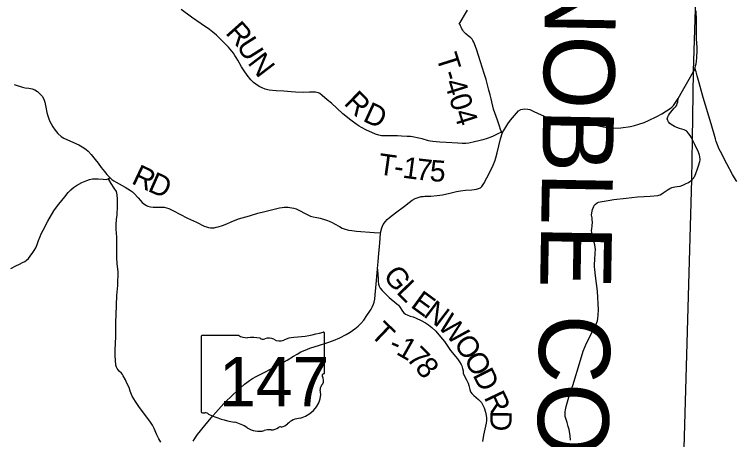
# Model space of a CAD drawing. Extents: x -10 to 158, y 8 to 33.
# Drawn here: x 151.875 to 153.801, y 28.492 to 29.627 of the extents above; entities that cross this region are included whole.
import ezdxf

# ---------------------------------------------------------------- set-up
doc = ezdxf.new("R2010")
doc.units = 0
for name, color, linetype in [('GM_X_County_Road', 7, 'Continuous'), ('GM_X_County_Road_Text', 7, 'Continuous'), ('GM_X_County_Text', 7, 'Continuous'), ('GM_X_State_Location', 7, 'Continuous'), ('GM_X_State_Route', 7, 'Continuous'), ('GM_X_State_Shield', 7, 'Continuous'), ('GM_X_Township_Road', 7, 'Continuous'), ('GM_X_Township_Road_Text', 7, 'Continuous'), ('GM_X_Township_Text', 7, 'Continuous')]:
    doc.layers.add(name, color=color, linetype=linetype)

msp = doc.modelspace()

# ---------------------------------------------------------------- linework, layer by layer
at = {"layer": 'GM_X_County_Road'}
msp.add_lwpolyline([(151.874, 29.4399), (151.8825, 29.4372), (151.8909, 29.4345), (151.8966, 29.4329), (151.9037, 29.4314), (151.9133, 29.4305), (151.9228, 29.4285), (151.9298, 29.4256), (151.9363, 29.4212), (151.9417, 29.4165), (151.9488, 29.4092), (151.9533, 29.4013), (151.9561, 29.3929), (151.9593, 29.3795), (151.9617, 29.3659), (151.9638, 29.3569), (151.9668, 29.3482), (151.9699, 29.3412), (151.9731, 29.335), (151.9778, 29.3275), (151.9839, 29.3182), (151.9911, 29.3092), (151.9997, 29.3016), (152.0071, 29.2965), (152.0164, 29.2923), (152.0467, 29.2791), (152.0563, 29.2738), (152.0656, 29.2672), (152.0718, 29.2618), (152.0798, 29.2537), (152.0908, 29.2399), (152.0982, 29.2298), (152.1067, 29.2183), (152.1152, 29.2082), (152.1221, 29.2002), (152.1301, 29.1915), (152.1352, 29.1868), (152.1409, 29.1829), (152.1467, 29.1797), (152.171, 29.1664), (152.1854, 29.1573), (152.1902, 29.1535), (152.1952, 29.149), (152.2055, 29.1376), (152.2116, 29.1305), (152.2163, 29.1254), (152.2232, 29.1193), (152.2274, 29.1168), (152.2316, 29.1153), (152.2384, 29.1134), (152.2453, 29.1126), (152.2506, 29.1123), (152.2564, 29.1124), (152.2674, 29.113), (152.2747, 29.1125), (152.2811, 29.1108), (152.287, 29.1088), (152.2996, 29.1031), (152.3166, 29.0936), (152.3375, 29.0832), (152.361, 29.0725), (152.3819, 29.0622), (152.3883, 29.0598), (152.3931, 29.0586), (152.3985, 29.0576), (152.4032, 29.0575), (152.4087, 29.0578), (152.4136, 29.059), (152.419, 29.0605), (152.4302, 29.064), (152.4421, 29.0685), (152.4541, 29.0735), (152.4732, 29.0812), (152.5026, 29.0895), (152.525, 29.0963), (152.5436, 29.1013), (152.5757, 29.1088), (152.5827, 29.1108), (152.5897, 29.112), (152.5955, 29.1128), (152.6012, 29.1128), (152.6058, 29.1126), (152.6106, 29.1119), (152.616, 29.1109), (152.6215, 29.1095), (152.627, 29.1078), (152.6327, 29.1053), (152.6401, 29.1019), (152.6474, 29.0977), (152.6601, 29.0911), (152.6656, 29.0888), (152.6725, 29.087), (152.6825, 29.0849), (152.6915, 29.0828), (152.7057, 29.079), (152.7106, 29.0774), (152.7159, 29.0752), (152.7232, 29.0719), (152.7298, 29.0681), (152.7428, 29.0609), (152.7499, 29.0563), (152.7551, 29.0543), (152.7667, 29.0512), (152.7762, 29.05), (152.7884, 29.0487), (152.8354, 29.0449), (152.8524, 29.0442)], dxfattribs=at)
at = {"layer": 'GM_X_State_Route'}
for points in [[(153.6886, 29.4751), (153.6915, 29.4809), (153.6929, 29.4848), (153.6941, 29.49), (153.6952, 29.4956), (153.6962, 29.5023), (153.697, 29.5114), (153.6974, 29.5174), (153.698, 29.5262), (153.6978, 29.5387), (153.6972, 29.5505), (153.6967, 29.5623), (153.6965, 29.5886), (153.6964, 29.6114), (153.6958, 29.6369)], [(153.8042, 29.1816), (153.7979, 29.1909), (153.7925, 29.2003), (153.7774, 29.2286), (153.7602, 29.2615), (153.7572, 29.2676), (153.7552, 29.2722), (153.7523, 29.2791), (153.749, 29.2882), (153.7469, 29.2951), (153.7354, 29.3355), (153.7146, 29.4059), (153.7037, 29.4446), (153.6979, 29.463), (153.6978, 29.4633), (153.6952, 29.4737), (153.6939, 29.4788), (153.6929, 29.4848)], [(152.3526, 28.4873), (152.3572, 28.4949), (152.3643, 28.5051), (152.3839, 28.5297), (152.4048, 28.5552), (152.4124, 28.5642), (152.4338, 28.5877), (152.4603, 28.6133), (152.4683, 28.6206), (152.4785, 28.6301), (152.4896, 28.6394), (152.4956, 28.6444), (152.5024, 28.6495), (152.5105, 28.6545), (152.5203, 28.6604), (152.5385, 28.6696), (152.5621, 28.6815), (152.5778, 28.6899), (152.6034, 28.7043), (152.6205, 28.7147), (152.6299, 28.7202), (152.6398, 28.7258), (152.6511, 28.731), (152.6639, 28.736), (152.6893, 28.7437), (152.7064, 28.7491), (152.7269, 28.7562), (152.7441, 28.7637), (152.7605, 28.7722), (152.7712, 28.7784), (152.7839, 28.7875), (152.7925, 28.7944), (152.8002, 28.8019), (152.8077, 28.811), (152.8163, 28.8233), (152.8244, 28.8349), (152.8276, 28.8401), (152.8302, 28.8455), (152.8336, 28.8534), (152.8354, 28.8589), (152.8374, 28.867), (152.8387, 28.878), (152.8398, 28.8971), (152.8442, 28.9466), (152.8445, 28.949), (152.8462, 28.9662), (152.8485, 28.9895), (152.8501, 29.0066), (152.8514, 29.0292), (152.8524, 29.0442), (152.856, 29.0576), (152.8598, 29.0661), (152.8655, 29.0745), (152.8704, 29.08), (152.8763, 29.0851), (152.8928, 29.0979), (152.9168, 29.1156), (152.9289, 29.125), (152.9374, 29.131), (152.9455, 29.1356), (152.9531, 29.1386), (152.9609, 29.1407), (152.9662, 29.1415), (152.9712, 29.1418), (152.9869, 29.1421), (153.0039, 29.1434), (153.0181, 29.1456), (153.0374, 29.1504), (153.0553, 29.1546), (153.0662, 29.1564), (153.0793, 29.1579), (153.0968, 29.1593), (153.1092, 29.1607), (153.1143, 29.1621), (153.1193, 29.1646), (153.1233, 29.1682), (153.1288, 29.1762), (153.1441, 29.2063), (153.1531, 29.225), (153.1577, 29.2358), (153.1604, 29.2447), (153.164, 29.2575), (153.1732, 29.2955), (153.1783, 29.312), (153.1872, 29.3264), (153.193, 29.3354), (153.1998, 29.3449), (153.2103, 29.3578), (153.2214, 29.3695), (153.2271, 29.3731), (153.2324, 29.3747), (153.2375, 29.3755), (153.2462, 29.3746), (153.251, 29.3732), (153.26, 29.3693), (153.2735, 29.363), (153.2955, 29.3532), (153.306, 29.3491), (153.3166, 29.3454), (153.3283, 29.3429), (153.3471, 29.3407), (153.3794, 29.3376), (153.4084, 29.3347), (153.422, 29.333), (153.435, 29.3302), (153.4477, 29.3273), (153.4582, 29.325), (153.4687, 29.3238), (153.4941, 29.3247), (153.5198, 29.3285), (153.5312, 29.331), (153.5424, 29.3343), (153.5562, 29.3392), (153.5684, 29.3442), (153.5902, 29.355), (153.6035, 29.3621), (153.6163, 29.3696), (153.6261, 29.3765), (153.6307, 29.3799), (153.6349, 29.3843), (153.6389, 29.3891), (153.6477, 29.4028), (153.659, 29.4238), (153.6731, 29.4487), (153.6886, 29.4751)]]:
    msp.add_lwpolyline(points, dxfattribs=at)
at = {"layer": 'GM_X_State_Shield'}
for p, q in [((152.4735, 28.7702), (152.377, 28.7702)), ((152.7033, 28.6705), (152.7033, 28.7752)), ((152.3738, 28.7668), (152.3738, 28.5667)), ((152.7033, 28.6705), (152.7033, 28.6705))]:
    msp.add_line(p, q, dxfattribs=at)
for centre, major_axis, start_param, end_param in [((152.3775, 28.7672), (0.00382, 0), 1.712693, 3.28349), ((152.4965, 28.7935), (0.037, 0), 4.042523, 4.731795), ((152.5859, 29.0431), (0.3495, 0), 4.814394, 5.042369), ((152.6997, 28.7756), (0.00367, 0), 6.141152, 7.989035), ((152.5088, 28.6579), (0.133, 0), 1.404758, 1.657858), ((152.539, 28.7683), (0.0107, 0), 3.836095, 5.185415), ((152.5547, 28.7451), (0.0222, 0), 0.950623, 2.079405), ((152.5833, 28.7768), (0.0267, 0), 4.081561, 5.145723), ((152.6305, 28.7091), (0.0703, 0), 1.699011, 2.107814), ((152.7025, 28.6628), (0.00568, 0), 1.883978, 3.671073), ((152.6664, 28.6496), (0.0341, 0), 5.934695, 6.695948), ((152.6994, 28.6701), (0.00393, 0), 5.05454, 6.418171), ((152.7165, 28.6267), (0.0248, 0), 2.387724, 3.262537), ((152.6055, 28.6134), (0.0874, 0), 5.101752, 6.440018), ((152.3776, 28.5662), (0.00385, 0), 3.00124, 4.508301), ((152.3782, 28.5867), (0.0294, 0), 4.665946, 4.897461), ((152.3842, 28.5551), (0.0106, 0), 0.519207, 1.627899), ((152.518, 28.7349), (0.2524, 0), 4.195997, 4.488961), ((152.6424, 28.5105), (0.0479, 0), 1.647645, 2.488434), ((152.4427, 28.4768), (0.079, 0), 0.823519, 1.323587), ((152.5282, 28.5541), (0.0501, 0), 4.026481, 4.996735), ((152.5608, 28.5391), (0.0267, 0), 4.691044, 5.507374), ((152.5849, 28.5198), (0.00752, 0), 1.147584, 2.315152), ((152.5817, 28.5473), (0.0282, 0), 4.937069, 5.64225), ((152.5571, 28.4849), (0.0412, 0), 1.495662, 1.94098)]:
    msp.add_ellipse(centre, major_axis=major_axis, ratio=0.8, start_param=start_param, end_param=end_param, dxfattribs=at)
at = {"layer": 'GM_X_Township_Road'}
for points in [[(153.1783, 29.312), (153.1735, 29.3118), (153.1695, 29.3106), (153.1587, 29.305), (153.153, 29.3023), (153.1475, 29.2999), (153.1376, 29.2963), (153.1258, 29.2928), (153.1147, 29.2897), (153.1038, 29.2871), (153.0883, 29.2833), (153.08, 29.2823), (153.0706, 29.2826), (153.0587, 29.2835), (153.0281, 29.2852), (153.011, 29.2861), (153.001, 29.287), (152.9925, 29.2878), (152.9861, 29.2888), (152.9805, 29.2902), (152.9634, 29.2947), (152.9503, 29.2979), (152.9426, 29.2995), (152.9379, 29.3004), (152.9323, 29.301), (152.9239, 29.3013), (152.9088, 29.3019), (152.8976, 29.303), (152.8906, 29.3035), (152.8785, 29.3035), (152.8629, 29.3029), (152.8554, 29.3034), (152.848, 29.305), (152.8396, 29.3078), (152.829, 29.3122), (152.8153, 29.3187), (152.8019, 29.3257), (152.796, 29.3286), (152.7906, 29.3321), (152.7729, 29.345), (152.7524, 29.3622), (152.7357, 29.3772), (152.7214, 29.3901), (152.7105, 29.3989), (152.6968, 29.4109), (152.6902, 29.4158), (152.6866, 29.4178), (152.6822, 29.4193), (152.6786, 29.42), (152.6748, 29.4201), (152.6632, 29.4198), (152.6478, 29.4189), (152.626, 29.4196), (152.6141, 29.4208), (152.5946, 29.4229), (152.574, 29.4237), (152.5552, 29.425), (152.5442, 29.4279), (152.5365, 29.4311), (152.5306, 29.4339), (152.5258, 29.4368), (152.5198, 29.4408), (152.5137, 29.4454), (152.5059, 29.4531), (152.4967, 29.4649), (152.4889, 29.4765), (152.4818, 29.4878), (152.4714, 29.5049), (152.467, 29.5127), (152.4639, 29.5179), (152.4599, 29.5239), (152.4463, 29.5396), (152.4227, 29.5641), (152.4144, 29.5722), (152.4048, 29.5803), (152.3959, 29.5869), (152.3737, 29.6023), (152.3481, 29.6201), (152.3199, 29.6402)], [(153.1783, 29.312), (153.1757, 29.3145), (153.174, 29.3172), (153.1694, 29.3319), (153.1651, 29.3447), (153.1545, 29.3747), (153.148, 29.4017), (153.1453, 29.4127), (153.1418, 29.4249), (153.1382, 29.4396), (153.1368, 29.4465), (153.1346, 29.454), (153.1303, 29.4672), (153.1237, 29.4863), (153.1192, 29.5005), (153.1085, 29.5343), (153.1014, 29.5534), (153.0993, 29.5575), (153.0969, 29.5612), (153.0935, 29.5648), (153.0865, 29.5707), (153.0805, 29.5753), (153.0766, 29.5789), (153.0743, 29.5816), (153.0721, 29.585), (153.0701, 29.5888), (153.0682, 29.5935), (153.0665, 29.5971), (153.0649, 29.5994), (153.063, 29.6018), (153.0845, 29.6388)], [(153.6858, 29.2924), (153.6817, 29.2995), (153.6794, 29.3037), (153.6762, 29.3089), (153.6733, 29.3124), (153.6702, 29.3153), (153.6672, 29.3174), (153.6637, 29.319), (153.6506, 29.3231), (153.6441, 29.3255), (153.6375, 29.3284), (153.6334, 29.3307), (153.629, 29.3335), (153.6254, 29.3365), (153.6219, 29.3402), (153.6195, 29.3443), (153.6184, 29.3485), (153.6188, 29.3508), (153.6195, 29.3535), (153.6214, 29.3573), (153.6247, 29.362), (153.6313, 29.3706), (153.6371, 29.3771), (153.641, 29.3816), (153.6435, 29.3854), (153.645, 29.3892), (153.6462, 29.394), (153.6477, 29.4028)], [(153.6844, 29.1856), (153.6859, 29.1872), (153.6891, 29.1912), (153.6904, 29.1933), (153.6916, 29.1953), (153.6958, 29.2055), (153.6984, 29.212), (153.7019, 29.2231), (153.7053, 29.235), (153.706, 29.238), (153.7062, 29.2398), (153.7057, 29.2476), (153.7044, 29.2517), (153.7016, 29.2591), (153.6986, 29.2662), (153.6959, 29.272), (153.6918, 29.2801), (153.6858, 29.2924)], [(151.8654, 28.9489), (151.8786, 28.9563), (151.8887, 28.9606), (151.8969, 28.9646), (151.9025, 28.9679), (151.907, 28.9714), (151.9123, 28.9758), (151.917, 28.9816), (151.924, 28.9912), (151.928, 28.997), (151.932, 29.0039), (151.9358, 29.0126), (151.9396, 29.0239), (151.9434, 29.0342), (151.9465, 29.0414), (151.9515, 29.0515), (151.9641, 29.0753), (151.9806, 29.1031), (151.9871, 29.1128), (151.9939, 29.1209), (152.0098, 29.14), (152.0187, 29.1515), (152.0256, 29.1587), (152.0327, 29.1654), (152.0406, 29.1708), (152.055, 29.1783), (152.0686, 29.184), (152.0759, 29.1865), (152.0839, 29.1881), (152.0982, 29.1882), (152.1119, 29.187), (152.12, 29.1867), (152.1254, 29.1881), (152.1301, 29.1915)], [(152.2656, 28.4846), (152.2607, 28.4937), (152.2556, 28.5042), (152.2481, 28.5211), (152.2439, 28.5299), (152.2368, 28.5409), (152.2086, 28.5775), (152.1981, 28.5935), (152.1897, 28.6075), (152.184, 28.6208), (152.1815, 28.6308), (152.1756, 28.6424), (152.1712, 28.6518), (152.1656, 28.6621), (152.1635, 28.6656), (152.1607, 28.6689), (152.1549, 28.6745), (152.149, 28.6814), (152.1475, 28.6848), (152.1461, 28.6904), (152.1441, 28.7167), (152.144, 28.7327), (152.1447, 28.7476), (152.1455, 28.7681), (152.1456, 28.7877), (152.1459, 28.8065), (152.1466, 28.8247), (152.1488, 28.8765), (152.1508, 28.9034), (152.1513, 28.9176), (152.1517, 28.9282), (152.1517, 28.9407), (152.1496, 28.9609), (152.1485, 28.9785), (152.1484, 29.0009), (152.1487, 29.0124), (152.1486, 29.0245), (152.1483, 29.0321), (152.1467, 29.0541), (152.1463, 29.066), (152.1473, 29.0795), (152.1497, 29.0924), (152.1506, 29.1151), (152.1507, 29.1339), (152.1494, 29.1459), (152.1473, 29.1547), (152.1415, 29.1635), (152.1335, 29.1754), (152.1267, 29.1863), (152.1301, 29.1915)], [(153.3599, 28.4905), (153.3588, 28.5015), (153.3563, 28.5189), (153.3541, 28.5271), (153.3508, 28.5378), (153.3477, 28.5484), (153.346, 28.5532), (153.3457, 28.5592), (153.3457, 28.5656), (153.3465, 28.5716), (153.3482, 28.5803), (153.3594, 28.6174), (153.3658, 28.6362), (153.3863, 28.7042), (153.3938, 28.7276), (153.3983, 28.7386), (153.4027, 28.7495), (153.4134, 28.77), (153.4168, 28.7782), (153.4229, 28.7895), (153.4258, 28.7943), (153.4288, 28.8004), (153.4316, 28.8089), (153.433, 28.8153), (153.434, 28.8237), (153.4345, 28.8386), (153.4324, 28.888), (153.4267, 28.9294), (153.4246, 28.9457), (153.4241, 28.953), (153.4243, 28.9609), (153.4246, 28.9714), (153.4258, 28.9906), (153.4263, 28.9998), (153.4258, 29.0056), (153.4248, 29.0123), (153.4182, 29.0386), (153.4167, 29.0452), (153.4163, 29.0499), (153.4166, 29.0549), (153.4179, 29.062), (153.4184, 29.073), (153.4182, 29.0776), (153.4175, 29.084), (153.4164, 29.0912), (153.4165, 29.0973), (153.4185, 29.106), (153.4205, 29.1111), (153.4218, 29.1139), (153.4234, 29.1167), (153.427, 29.121), (153.4313, 29.1242), (153.4351, 29.126), (153.4392, 29.1272), (153.4608, 29.1304), (153.4757, 29.1328), (153.5089, 29.137), (153.5392, 29.1402), (153.5569, 29.1414), (153.5726, 29.1421), (153.583, 29.1427), (153.5932, 29.1438), (153.5961, 29.1446), (153.5992, 29.1457), (153.6039, 29.1483), (153.6074, 29.1506), (153.6152, 29.1565), (153.6207, 29.1598), (153.6248, 29.1622), (153.6304, 29.1647), (153.6347, 29.166), (153.6389, 29.1667), (153.645, 29.1676), (153.6524, 29.169), (153.6595, 29.1713), (153.6673, 29.1748), (153.6747, 29.1789), (153.6844, 29.1856)], [(152.8442, 28.9466), (152.8458, 28.9314), (152.846, 28.9232), (152.846, 28.9139), (152.8468, 28.9071), (152.8487, 28.9018), (152.8517, 28.8964), (152.857, 28.8904), (152.8664, 28.8801), (152.8758, 28.8714), (152.8958, 28.8545), (152.9003, 28.8506), (152.9033, 28.8472), (152.9117, 28.8344), (152.9147, 28.8306), (152.9189, 28.8271), (152.9239, 28.8247), (152.9319, 28.8218), (152.9402, 28.8193), (152.9478, 28.8162), (152.9607, 28.8098), (152.9724, 28.8036), (152.9811, 28.7981), (152.9895, 28.7915), (153.0003, 28.7812), (153.013, 28.7665), (153.0233, 28.7539), (153.0326, 28.7403), (153.0393, 28.7301), (153.0583, 28.7071), (153.0636, 28.6998), (153.0678, 28.6926), (153.0698, 28.6884), (153.0715, 28.6818), (153.0729, 28.6751), (153.0736, 28.6687), (153.0821, 28.6518), (153.0865, 28.6422), (153.0881, 28.6364), (153.0907, 28.6258), (153.093, 28.6197), (153.0963, 28.6151), (153.1014, 28.6093), (153.1141, 28.5986), (153.122, 28.5911), (153.1259, 28.584), (153.1293, 28.5763), (153.1326, 28.5646), (153.1345, 28.5564), (153.1353, 28.55), (153.1355, 28.5429), (153.1349, 28.5354), (153.1278, 28.5032), (153.125, 28.4868)]]:
    msp.add_lwpolyline(points, dxfattribs=at)
at = {"layer": 'GM_X_Township_Text'}
msp.add_lwpolyline([(153.6265, 25.0623), (153.6357, 26.4561), (153.6472, 27.3472), (153.6542, 27.6186), (153.661, 28.3755), (153.6842, 29.1862), (153.6856, 29.293), (153.6884, 29.4756), (153.6987, 29.8088), (153.7008, 29.9089), (153.703, 29.918), (153.6996, 30.0615), (153.6575, 30.0619)], dxfattribs=at)

# ---------------------------------------------------------------- texts
at = {"layer": 'GM_X_County_Road_Text'}
for s, rotation, p in [('R', 334.7843, (152.1849, 29.1771)), ('D', 335.969, (152.2283, 29.1567))]:
    msp.add_text(s, height=0.0568, rotation=rotation, dxfattribs=at).set_placement(p)
at = {"layer": 'GM_X_County_Text'}
msp.add_text('NOBLE COUNTY', height=0.189394, rotation=269.0214, dxfattribs=at).set_placement((153.2934, 29.7558))
at = {"layer": 'GM_X_State_Location'}
msp.add_text('147', height=0.000189, rotation=0, dxfattribs=at).set_placement((152.468, 28.6396))
for s, p in [('s', (152.5349, 28.6534)), ('r', (152.5348, 28.6534))]:
    msp.add_text(s, height=0.000189, dxfattribs=at).set_placement(p)
at = {"layer": 'GM_X_State_Shield'}
msp.add_text('147', height=0.13184, dxfattribs=at).set_placement((152.4216, 28.5808))
at = {"layer": 'GM_X_Township_Road_Text'}
for s, height, rotation, p in [('R', 0.0568, 311.7444, (152.4366, 29.5773)), ('U', 0.0568, 302.417, (152.4662, 29.5445)), ('N', 0.0568, 307.3655, (152.4961, 29.4979)), ('T-404', 0.05682, 287.4332, (153.0006, 29.5146)), ('R', 0.0568, 315.5133, (152.7522, 29.3884)), ('D', 0.0568, 335.336, (152.8028, 29.3438)), ('T', 0.0568, 352.0893, (152.8439, 29.2007)), ('1', 0.0568, 352.5077, (152.9096, 29.1916)), ('7', 0.0568, 353.359, (152.9452, 29.1869)), ('5', 0.0568, 355.6513, (152.9824, 29.1827)), ('-', 0.0568, 352.1762, (152.8861, 29.1948)), ('G', 0.0568, 307.6932, (152.8575, 28.9294)), ('L', 0.0568, 314.28, (152.8928, 28.8845)), ('E', 0.0568, 323.8527, (152.9303, 28.8473)), ('N', 0.0568, 322.8161, (152.9644, 28.8224)), ('W', 0.0568, 313.3076, (153.0024, 28.7938)), ('T', 0.0568, 316.3759, (152.8227, 28.771)), ('-', 0.0568, 336.703, (152.8717, 28.7297)), ('1', 0.0568, 330.5152, (152.8917, 28.7212)), ('O', 0.0568, 305.4928, (153.0462, 28.7475)), ('7', 0.0568, 314.448, (152.9188, 28.7065)), ('O', 0.0568, 297.7854, (153.0742, 28.7085)), ('8', 0.0568, 309.5717, (152.9425, 28.6825)), ('D', 0.0568, 296.8502, (153.0974, 28.6645)), ('R', 0.0568, 295.4654, (153.1277, 28.6046)), ('D', 0.0568, 269.3224, (153.1463, 28.5691))]:
    msp.add_text(s, height=height, rotation=rotation, dxfattribs=at).set_placement(p)

doc.saveas('drawing.dxf')
